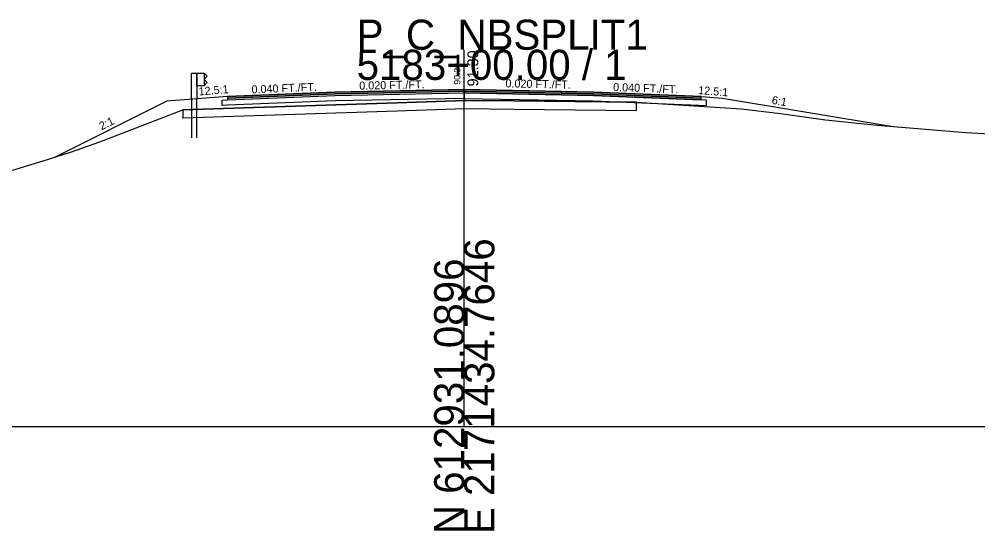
# Model space of a CAD drawing. Extents: x -26 to 1303, y -3010 to 12038.
# Drawn here: x 108.6 to 197.7, y 4990.3 to 5037.8 of the extents above; entities that cross this region are included whole.
import ezdxf

# ---------------------------------------------------------------- set-up
doc = ezdxf.new("R2010")
doc.units = 0
for name, color, linetype in [('RD_GPK_XS_Cell', 7, 'Continuous'), ('RD_PD_Final_TrvlWay', 7, 'Continuous'), ('RD_XS_Base', 7, 'Continuous'), ('RD_XS_ExGround', 7, 'Continuous'), ('RD_XS_ExPaveRet', 7, 'Continuous'), ('RD_XS_GR', 7, 'Continuous'), ('RD_XS_Greenside', 7, 'Continuous'), ('RD_XS_Pave', 7, 'Continuous'), ('RD_XS_PaveOvlay_CP', 7, 'Continuous'), ('RD_XS_TieSlope', 7, 'Continuous'), ('RD_XS_TX_Elev_EX', 7, 'Continuous'), ('RD_XS_TX_Elev_PR', 7, 'Continuous'), ('RD_XS_TX_ShdSlope', 7, 'Continuous'), ('RD_XS_TX_Slope', 7, 'Continuous')]:
    doc.layers.add(name, color=color, linetype=linetype)

msp = doc.modelspace()

# ---------------------------------------------------------------- linework, layer by layer
at = {"layer": 'RD_GPK_XS_Cell'}
for p, q in [((150, 5000), (150, 5035)), ((0, 5000), (150, 5000)), ((150, 5000), (300, 5000))]:
    msp.add_line(p, q, dxfattribs=at)
at = {"layer": 'RD_PD_Final_TrvlWay'}
for p, q in [((125.167, 5030.435), (124.667, 5030.395)), ((124.667, 5030.395), (124.667, 5026.83)), ((125.167, 5026.83), (125.167, 5030.435))]:
    msp.add_line(p, q, dxfattribs=at)
at = {"layer": 'RD_XS_Base'}
for p, q in [((128, 5030.344), (138, 5030.744)), ((138, 5030.744), (150, 5030.984)), ((138, 5030.744), (138, 5030.744)), ((150, 5030.984), (150, 5031.143)), ((150, 5031.143), (150, 5030.484)), ((150, 5030.984), (150, 5030.484)), ((162, 5030.744), (150, 5030.984)), ((150, 5030.984), (150, 5030.984)), ((172, 5030.344), (162, 5030.743)), ((164, 5030.664), (164, 5030.664)), ((127.5, 5030.324), (128, 5030.344)), ((127.5, 5029.824), (127.5, 5030.324)), ((127.5, 5030.324), (127.5, 5030.324)), ((128, 5029.844), (127.5, 5029.824)), ((127.5, 5029.824), (127.5, 5029.824)), ((127.5, 5029.824), (127.5, 5029.824)), ((128, 5030.344), (128, 5030.344)), ((138, 5030.244), (128, 5029.844)), ((128, 5029.844), (128, 5029.844)), ((150, 5030.484), (138, 5030.244)), ((138, 5030.244), (138, 5030.244)), ((150, 5030.484), (150, 5030.484)), ((150, 5030.484), (150, 5030.484)), ((150, 5030.484), (162, 5030.244)), ((162, 5030.243), (172.5, 5029.824)), ((164, 5030.164), (164, 5030.164)), ((172.5, 5030.324), (172, 5030.344)), ((172, 5030.344), (172, 5030.344)), ((172.5, 5029.824), (172.5, 5030.324)), ((172.5, 5030.324), (172.5, 5030.324)), ((172.5, 5029.824), (172.5, 5029.824)), ((172.5, 5029.824), (172.5, 5029.824))]:
    msp.add_line(p, q, dxfattribs=at)
at = {"layer": 'RD_XS_ExGround'}
msp.add_lwpolyline([(104.788, 5022.809), (111.288, 5024.793), (113.413, 5025.472), (116.132, 5026.45), (123.842, 5029.411), (143.774, 5030.076), (150.039, 5030.301), (154.61, 5030.24), (166.006, 5030.119), (173.762, 5029.626), (175.772, 5029.504), (179.388, 5029.065), (183.553, 5028.501), (188.373, 5027.98), (196.598, 5027.31), (200.51, 5027.086)], dxfattribs=at)
at = {"layer": 'RD_XS_ExPaveRet'}
for p, q in [((143.774, 5030.076), (123.842, 5029.411)), ((150.039, 5030.301), (143.774, 5030.076)), ((154.61, 5030.24), (150.039, 5030.301)), ((166.006, 5030.119), (154.61, 5030.24))]:
    msp.add_line(p, q, dxfattribs=at)
for points in [[(154.61, 5030.24), (150.039, 5030.301), (150.039, 5030.301), (150.039, 5030.301), (143.774, 5030.076), (143.774, 5030.076), (123.842, 5029.411), (123.842, 5029.41), (123.842, 5029.41), (123.842, 5028.66), (123.842, 5028.661), (143.774, 5029.326), (143.774, 5029.326), (150.039, 5029.551), (150.039, 5029.551), (150.039, 5029.551), (154.61, 5029.49), (154.61, 5029.49), (166.006, 5029.369), (166.006, 5030.119), (166.006, 5030.119), (154.61, 5030.24), (154.61, 5030.24)], [(123.842, 5029.411), (123.842, 5029.41), (123.842, 5028.66), (123.842, 5028.661), (143.774, 5029.326), (150.039, 5029.551), (154.61, 5029.49), (166.006, 5029.369), (166.006, 5030.119)]]:
    msp.add_lwpolyline(points, dxfattribs=at)
at = {"layer": 'RD_XS_GR'}
for points in [[(125.167, 5032.83), (125.167, 5030.435), (124.667, 5030.395), (124.667, 5032.83), (124.917, 5032.83), (125.167, 5032.83)], [(125.834, 5032.83), (125.834, 5031.663), (125.167, 5031.663), (125.167, 5032.83), (125.834, 5032.83)], [(126.105, 5032.538), (125.834, 5032.83), (125.834, 5031.663), (125.834, 5031.663), (125.834, 5031.663), (126.105, 5031.955), (126.105, 5031.955), (125.834, 5032.247), (125.834, 5032.247), (126.105, 5032.538), (126.105, 5032.538)]]:
    msp.add_lwpolyline(points, dxfattribs=at)
at = {"layer": 'RD_XS_Greenside'}
for p, q in [((122.355, 5030.21), (111.932, 5024.999)), ((174, 5030.502), (189.855, 5027.859))]:
    msp.add_line(p, q, dxfattribs=at)
at = {"layer": 'RD_XS_Pave'}
for p, q in [((138, 5031.062), (128, 5030.662)), ((138, 5030.903), (128, 5030.503)), ((128, 5030.503), (138, 5030.903)), ((128, 5030.344), (138, 5030.744)), ((128, 5030.662), (128, 5030.662)), ((128, 5030.662), (128, 5030.503)), ((150, 5031.302), (138, 5031.062)), ((150, 5031.143), (138, 5030.903)), ((138, 5030.903), (150, 5031.143)), ((138, 5031.062), (138, 5031.062)), ((138, 5030.744), (150, 5030.984)), ((138, 5030.903), (138, 5030.903)), ((138, 5030.903), (138, 5030.903)), ((138, 5030.744), (138, 5030.744)), ((162, 5031.062), (150, 5031.302)), ((150, 5030.984), (150, 5031.143)), ((150, 5031.143), (162, 5030.903)), ((162, 5030.903), (150, 5031.143)), ((150, 5031.143), (150, 5030.984)), ((150, 5030.984), (150, 5030.984)), ((150, 5030.984), (150, 5030.984)), ((150, 5030.984), (162, 5030.744)), ((172, 5030.662), (162, 5031.062)), ((162, 5030.902), (172, 5030.503)), ((172, 5030.503), (162, 5030.902)), ((162, 5030.743), (172, 5030.344)), ((164, 5030.982), (164, 5030.982)), ((164, 5030.823), (164, 5030.823)), ((164, 5030.823), (164, 5030.823)), ((164, 5030.664), (164, 5030.664)), ((172, 5030.503), (172, 5030.662)), ((172, 5030.662), (172, 5030.662)), ((128, 5030.503), (128, 5030.503)), ((128, 5030.503), (128, 5030.344)), ((128, 5030.503), (128, 5030.503)), ((128, 5030.503), (128, 5030.503)), ((128, 5030.344), (128, 5030.344)), ((128, 5030.344), (128, 5030.344)), ((172, 5030.503), (172, 5030.503)), ((172, 5030.503), (172, 5030.503)), ((172, 5030.344), (172, 5030.503)), ((172, 5030.503), (172, 5030.503)), ((172, 5030.344), (172, 5030.344)), ((172, 5030.344), (172, 5030.344))]:
    msp.add_line(p, q, dxfattribs=at)
at = {"layer": 'RD_XS_PaveOvlay_CP'}
for p, q in [((128, 5030.662), (138, 5031.062)), ((138, 5031.062), (150, 5031.302)), ((150, 5031.302), (162, 5031.062)), ((162, 5031.062), (172, 5030.662))]:
    msp.add_line(p, q, dxfattribs=at)
at = {"layer": 'RD_XS_TieSlope'}
for p, q in [((128, 5030.662), (122.355, 5030.21)), ((172, 5030.662), (174, 5030.502))]:
    msp.add_line(p, q, dxfattribs=at)

# ---------------------------------------------------------------- texts
at = {"layer": 'RD_GPK_XS_Cell'}
for s, p in [('P_C_NBSPLIT1', (140, 5035)), ('5183+00.00 / 1', (140, 5032.2))]:
    msp.add_text(s, height=2.8, dxfattribs=at).set_placement(p)
for s, p in [('E 2171434.7646', (152.8, 4990)), ('N 612931.0896', (150, 4990))]:
    msp.add_text(s, height=2.8, rotation=90, dxfattribs=at).set_placement(p)
at = {"layer": 'RD_XS_TX_Elev_EX'}
msp.add_text('90.30', height=0.6, rotation=90, dxfattribs=at).set_placement((149.639, 5031.759))
at = {"layer": 'RD_XS_TX_Elev_PR'}
msp.add_text('91.30', height=1, rotation=90, dxfattribs=at).set_placement((151.297, 5031.593))
at = {"layer": 'RD_XS_TX_ShdSlope'}
for rotation, p in [(4.57392, (125.35, 5030.751)), (355.42608, (171.711, 5030.888))]:
    msp.add_text('12.5:1', height=0.75, rotation=rotation, dxfattribs=at).set_placement(p)
at = {"layer": 'RD_XS_TX_Slope'}
for s, rotation, p in [('0.040 FT./FT.', 2.29061, (130.247, 5030.937)), ('0.020 FT./FT.', 1.14576, (140.248, 5031.292)), ('0.020 FT./FT.', 358.85424, (153.822, 5031.507)), ('0.040 FT./FT.', 357.70939, (163.815, 5031.178)), ('6:1', 350.53768, (178.529, 5029.98)), ('2:1', 26.56505, (116.301, 5027.516))]:
    msp.add_text(s, height=0.75, rotation=rotation, dxfattribs=at).set_placement(p)

doc.saveas('drawing.dxf')
